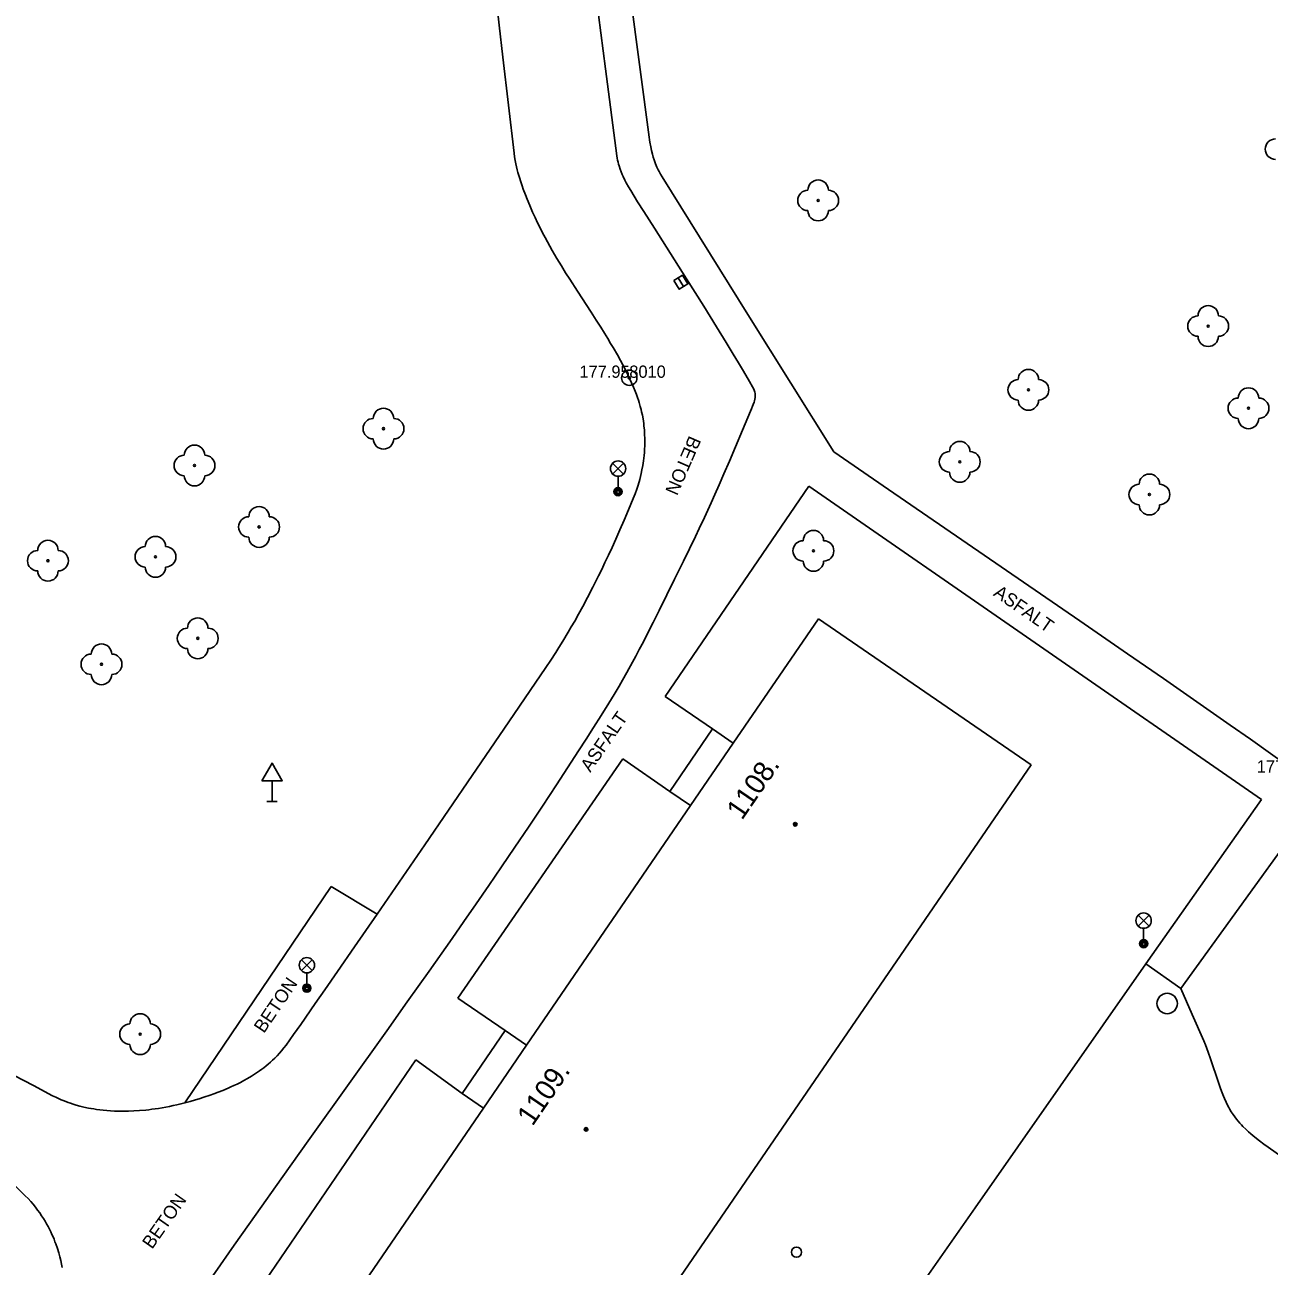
# Model space of a CAD drawing. Extents: x -539515 to -538098, y -1182060 to -1180157.
# Drawn here: x -538886.7 to -538825.8, y -1181224.5 to -1181163.7 of the extents above; entities that cross this region are included whole.
import ezdxf

# ---------------------------------------------------------------- set-up
doc = ezdxf.new("R2010")
doc.units = 0
for name, color, linetype in [('Vrstva 1', 7, 'Continuous'), ('Vrstva 13', 7, 'Continuous'), ('Vrstva 21', 7, 'Continuous'), ('Vrstva 22', 7, 'Continuous'), ('Vrstva 23', 7, 'Continuous'), ('Vrstva 27', 7, 'Continuous'), ('Vrstva 31', 7, 'Continuous'), ('Vrstva 33', 7, 'Continuous'), ('Vrstva 34', 7, 'Continuous'), ('Vrstva 39', 7, 'Continuous'), ('Vrstva 40', 7, 'Continuous'), ('Vrstva 47', 7, 'Continuous'), ('Vrstva 88', 7, 'Continuous')]:
    doc.layers.add(name, color=color, linetype=linetype)

msp = doc.modelspace()

# ---------------------------------------------------------------- linework, layer by layer
at = {"layer": 'Vrstva 1'}
for p, q in [((-538847.83, -1181192.78), (-538837.41, -1181199.92)), ((-538853.007, -1181198.163), (-538855.1, -1181201.22)), ((-538851.991, -1181198.859), (-538853.007, -1181198.163)), ((-538837.41, -1181199.92), (-538868.14, -1181244.73)), ((-538854.083, -1181201.916), (-538855.1, -1181201.22)), ((-538863.155, -1181212.925), (-538865.26, -1181216)), ((-538862.109, -1181213.641), (-538863.155, -1181212.925)), ((-538864.214, -1181216.716), (-538865.26, -1181216))]:
    msp.add_line(p, q, dxfattribs=at)
for points in [[(-538851.991, -1181198.859), (-538847.83, -1181192.78)], [(-538854.083, -1181201.916), (-538851.991, -1181198.859)], [(-538862.109, -1181213.641), (-538854.083, -1181201.916)], [(-538864.214, -1181216.716), (-538862.109, -1181213.641)], [(-538872.38, -1181228.646), (-538864.214, -1181216.716)]]:
    msp.add_lwpolyline(points, dxfattribs=at)
at = {"layer": 'Vrstva 13'}
for p, q in [((-538857.05, -1181162.12), (-538856.11, -1181169.2)), ((-538855.48, -1181171.15), (-538851.275, -1181177.875)), ((-538851.275, -1181177.875), (-538847.07, -1181184.6)), ((-538847.07, -1181184.6), (-538844.398, -1181186.442)), ((-538855.32, -1181196.58), (-538848.29, -1181186.29)), ((-538848.29, -1181186.29), (-538826.14, -1181201.62)), ((-538844.398, -1181186.442), (-538835.034, -1181192.872)), ((-538853.007, -1181198.163), (-538855.32, -1181196.58)), ((-538865.47, -1181211.34), (-538857.4, -1181199.63)), ((-538857.4, -1181199.63), (-538855.1, -1181201.22)), ((-538826.14, -1181201.62), (-538831.8, -1181209.66)), ((-538830.09, -1181210.86), (-538824.35, -1181202.91)), ((-538871.67, -1181205.87), (-538878.83, -1181216.46)), ((-538869.42, -1181207.22), (-538871.67, -1181205.87)), ((-538831.8, -1181209.66), (-538830.09, -1181210.86)), ((-538863.155, -1181212.925), (-538865.47, -1181211.34)), ((-538875.72, -1181226.36), (-538867.52, -1181214.36)), ((-538867.52, -1181214.36), (-538865.26, -1181216))]:
    msp.add_line(p, q, dxfattribs=at)
for points in [[(-538856.11, -1181169.2), (-538856.092, -1181169.327), (-538856.073, -1181169.446), (-538856.032, -1181169.67), (-538855.99, -1181169.865), (-538855.948, -1181170.035), (-538855.906, -1181170.182), (-538855.866, -1181170.309), (-538855.828, -1181170.419), (-538855.793, -1181170.515), (-538855.726, -1181170.679), (-538855.671, -1181170.801), (-538855.627, -1181170.89), (-538855.556, -1181171.022), (-538855.48, -1181171.15)], [(-538835.034, -1181192.872), (-538832.696, -1181194.485), (-538830.945, -1181195.697), (-538829.634, -1181196.609), (-538827.67, -1181197.981)], [(-538827.67, -1181197.981), (-538826.689, -1181198.67), (-538825.71, -1181199.36), (-538825.087, -1181199.804), (-538824.158, -1181200.476), (-538824.08, -1181200.48), (-538823.23, -1181201.15)]]:
    msp.add_lwpolyline(points, dxfattribs=at)
at = {"layer": 'Vrstva 21'}
for radius in [0.375, 0.05]:
    msp.add_circle((-538857.08, -1181180.98), radius, dxfattribs=at)
at = {"layer": 'Vrstva 22'}
for centre in [(-538847.84, -1181172.3), (-538828.75, -1181178.45), (-538837.55, -1181181.57), (-538826.78, -1181182.47), (-538869.11, -1181183.47), (-538878.36, -1181185.27), (-538840.91, -1181185.09), (-538831.63, -1181186.69), (-538875.2, -1181188.28), (-538880.27, -1181189.74), (-538848.07, -1181189.45), (-538885.53, -1181189.93), (-538878.2, -1181193.73), (-538882.91, -1181195), (-538881.02, -1181213.1)]:
    msp.add_circle(centre, 0.05, dxfattribs=at)
for centre, start, end in [((-538825.46, -1181169.79), 90, 270), ((-538847.84, -1181171.8), 0, 180), ((-538848.34, -1181172.3), 90, 270), ((-538847.34, -1181172.3), 270, 90), ((-538847.84, -1181172.8), 180, 0), ((-538828.75, -1181177.95), 0, 180), ((-538829.25, -1181178.45), 90, 270), ((-538828.25, -1181178.45), 270, 90), ((-538828.75, -1181178.95), 180, 0), ((-538837.55, -1181181.07), 0, 180), ((-538838.05, -1181181.57), 90, 270), ((-538837.05, -1181181.57), 270, 90), ((-538826.78, -1181181.97), 0, 180), ((-538837.55, -1181182.07), 180, 0), ((-538827.28, -1181182.47), 90, 270), ((-538826.28, -1181182.47), 270, 90), ((-538869.61, -1181183.47), 90, 270), ((-538869.11, -1181182.97), 0, 180), ((-538868.61, -1181183.47), 270, 90), ((-538826.78, -1181182.97), 180, 0), ((-538878.36, -1181184.77), 0, 180), ((-538869.11, -1181183.97), 180, 0), ((-538840.91, -1181184.59), 0, 180), ((-538878.86, -1181185.27), 90, 270), ((-538877.86, -1181185.27), 270, 90), ((-538841.41, -1181185.09), 90, 270), ((-538840.41, -1181185.09), 270, 90), ((-538878.36, -1181185.77), 180, 0), ((-538840.91, -1181185.59), 180, 0), ((-538831.63, -1181186.19), 0, 180), ((-538832.13, -1181186.69), 90, 270), ((-538831.13, -1181186.69), 270, 90), ((-538875.2, -1181187.78), 0, 180), ((-538831.63, -1181187.19), 180, 0), ((-538875.7, -1181188.28), 90, 270), ((-538874.7, -1181188.28), 270, 90), ((-538848.07, -1181188.95), 0, 180), ((-538885.53, -1181189.43), 0, 180), ((-538880.27, -1181189.24), 0, 180), ((-538875.2, -1181188.78), 180, 0), ((-538848.57, -1181189.45), 90, 270), ((-538847.57, -1181189.45), 270, 90), ((-538886.03, -1181189.93), 90, 270), ((-538885.03, -1181189.93), 270, 90), ((-538880.77, -1181189.74), 90, 270), ((-538879.77, -1181189.74), 270, 90), ((-538880.27, -1181190.24), 180, 0), ((-538848.07, -1181189.95), 180, 0), ((-538885.53, -1181190.43), 180, 0), ((-538878.2, -1181193.23), 0, 180), ((-538878.7, -1181193.73), 90, 270), ((-538877.7, -1181193.73), 270, 90), ((-538882.91, -1181194.5), 0, 180), ((-538883.41, -1181195), 90, 270), ((-538882.41, -1181195), 270, 90), ((-538878.2, -1181194.23), 180, 0), ((-538882.91, -1181195.5), 180, 0), ((-538881.02, -1181212.6), 0, 180), ((-538881.52, -1181213.1), 90, 270), ((-538880.52, -1181213.1), 270, 90), ((-538881.02, -1181213.6), 180, 0)]:
    msp.add_arc(centre, 0.5, start, end, dxfattribs=at)
at = {"layer": 'Vrstva 27'}
msp.add_line((-538854.69, -1181176.092), (-538854.424, -1181176.516), dxfattribs=at)
msp.add_lwpolyline([(-538854.902, -1181176.225), (-538854.636, -1181176.649), (-538854.212, -1181176.383), (-538854.478, -1181175.959)], close=True, dxfattribs=at)
msp.add_circle((-538830.76, -1181211.6), 0.5, dxfattribs=at)
at = {"layer": 'Vrstva 31'}
msp.add_circle((-538848.9, -1181223.77), 0.25, dxfattribs=at)
at = {"layer": 'Vrstva 33'}
for p, q in [((-538857.895, -1181185.69), (-538857.365, -1181185.16)), ((-538857.895, -1181185.16), (-538857.365, -1181185.69)), ((-538857.63, -1181185.8), (-538857.63, -1181186.55)), ((-538832.175, -1181207.81), (-538831.645, -1181207.28)), ((-538832.175, -1181207.28), (-538831.645, -1181207.81)), ((-538831.91, -1181207.92), (-538831.91, -1181208.67)), ((-538873.125, -1181209.99), (-538872.595, -1181209.46)), ((-538873.125, -1181209.46), (-538872.595, -1181209.99)), ((-538872.86, -1181210.1), (-538872.86, -1181210.85))]:
    msp.add_line(p, q, dxfattribs=at)
for centre, radius in [((-538857.63, -1181185.425), 0.375), ((-538857.63, -1181186.55), 0.2), ((-538857.63, -1181186.55), 0.145), ((-538857.63, -1181186.55), 0.0876), ((-538831.91, -1181207.545), 0.375), ((-538831.91, -1181208.67), 0.2), ((-538831.91, -1181208.67), 0.145), ((-538831.91, -1181208.67), 0.0876), ((-538872.86, -1181209.725), 0.375), ((-538872.86, -1181210.85), 0.2), ((-538872.86, -1181210.85), 0.145), ((-538872.86, -1181210.85), 0.0876)]:
    msp.add_circle(centre, radius, dxfattribs=at)
at = {"layer": 'Vrstva 34'}
for p, q in [((-538874.564, -1181200.697), (-538874.564, -1181201.715)), ((-538874.814, -1181201.715), (-538874.314, -1181201.715))]:
    msp.add_line(p, q, dxfattribs=at)
msp.add_lwpolyline([(-538875.064, -1181200.697), (-538874.064, -1181200.697), (-538874.564, -1181199.831)], close=True, dxfattribs=at)
at = {"layer": 'Vrstva 39'}
for centre, radius in [((-538848.962, -1181202.831), 0.09), ((-538848.962, -1181202.831), 0.0398), ((-538859.192, -1181217.758), 0.09), ((-538859.192, -1181217.758), 0.0398)]:
    msp.add_circle(centre, radius, dxfattribs=at)
at = {"layer": 'Vrstva 88'}
for p, q in [((-538858.795, -1181161.59), (-538858.242, -1181165.855)), ((-538859.124, -1181191.735), (-538859.358, -1181192.173)), ((-538831.8, -1181209.66), (-538840.16, -1181221.6)), ((-538868.946, -1181212.929), (-538872.711, -1181218.197)), ((-538840.16, -1181221.6), (-538848.52, -1181233.54))]:
    msp.add_line(p, q, dxfattribs=at)
for points in [[(-538863.682, -1181161.642), (-538863.451, -1181163.727), (-538863.273, -1181165.29), (-538863, -1181167.635), (-538862.72, -1181169.98), (-538862.694, -1181170.168), (-538862.665, -1181170.342), (-538862.633, -1181170.505), (-538862.6, -1181170.657), (-538862.565, -1181170.799), (-538862.53, -1181170.932), (-538862.459, -1181171.179), (-538862.391, -1181171.394)], [(-538858.242, -1181165.855), (-538857.69, -1181170.12), (-538857.673, -1181170.233), (-538857.653, -1181170.338), (-538857.631, -1181170.436), (-538857.607, -1181170.528), (-538857.582, -1181170.613), (-538857.53, -1181170.771), (-538857.479, -1181170.908), (-538857.43, -1181171.026), (-538857.384, -1181171.129), (-538857.299, -1181171.307), (-538857.231, -1181171.438), (-538857.123, -1181171.631), (-538857.01, -1181171.82), (-538856.673, -1181172.365), (-538856.376, -1181172.839), (-538855.852, -1181173.665), (-538855.064, -1181174.9)], [(-538862.391, -1181171.394), (-538862.328, -1181171.581), (-538862.269, -1181171.744), (-538862.162, -1181172.028), (-538862.077, -1181172.24), (-538861.946, -1181172.556), (-538861.81, -1181172.87), (-538861.689, -1181173.14), (-538861.568, -1181173.398)], [(-538861.568, -1181173.398), (-538861.447, -1181173.646), (-538861.326, -1181173.883), (-538861.206, -1181174.112), (-538861.087, -1181174.331), (-538860.97, -1181174.542), (-538860.854, -1181174.746), (-538860.625, -1181175.136), (-538860.405, -1181175.499), (-538860.196, -1181175.837), (-538859.996, -1181176.152), (-538859.617, -1181176.74), (-538858.948, -1181177.768), (-538858.699, -1181178.155), (-538858.482, -1181178.496), (-538858.295, -1181178.797), (-538858.133, -1181179.062), (-538857.993, -1181179.295), (-538857.873, -1181179.5), (-538857.665, -1181179.862), (-538857.513, -1181180.137), (-538857.402, -1181180.345), (-538857.238, -1181180.661), (-538857.08, -1181180.98), (-538856.966, -1181181.224), (-538856.872, -1181181.439), (-538856.795, -1181181.628), (-538856.731, -1181181.795), (-538856.679, -1181181.942), (-538856.636, -1181182.07)], [(-538855.064, -1181174.9), (-538854.671, -1181175.519), (-538854.28, -1181176.14), (-538853.438, -1181177.481), (-538852.808, -1181178.488)], [(-538852.808, -1181178.488), (-538852.341, -1181179.246), (-538851.995, -1181179.816), (-538851.738, -1181180.245), (-538851.548, -1181180.568), (-538851.267, -1181181.053), (-538850.99, -1181181.54), (-538850.95, -1181181.63), (-538850.934, -1181181.687), (-538850.925, -1181181.743), (-538850.92, -1181181.796), (-538850.92, -1181181.847), (-538850.922, -1181181.895), (-538850.927, -1181181.941), (-538850.941, -1181182.027), (-538850.958, -1181182.104), (-538850.977, -1181182.17), (-538851.016, -1181182.287), (-538851.048, -1181182.373)], [(-538856.6, -1181182.183), (-538856.543, -1181182.381), (-538856.504, -1181182.53), (-538856.477, -1181182.642), (-538856.441, -1181182.811), (-538856.41, -1181182.98), (-538856.391, -1181183.1), (-538856.375, -1181183.216), (-538856.362, -1181183.329), (-538856.341, -1181183.55), (-538856.329, -1181183.759), (-538856.323, -1181183.955), (-538856.322, -1181184.14), (-538856.326, -1181184.314), (-538856.334, -1181184.478), (-538856.345, -1181184.631), (-538856.358, -1181184.775), (-538856.372, -1181184.91), (-538856.389, -1181185.036), (-538856.425, -1181185.273), (-538856.463, -1181185.479), (-538856.501, -1181185.659), (-538856.538, -1181185.816), (-538856.573, -1181185.953), (-538856.605, -1181186.072), (-538856.668, -1181186.28), (-538856.718, -1181186.434), (-538856.8, -1181186.663), (-538856.844, -1181186.777), (-538856.89, -1181186.89), (-538857.12, -1181187.44), (-538857.338, -1181187.951), (-538857.544, -1181188.426), (-538857.741, -1181188.869), (-538857.927, -1181189.281), (-538858.104, -1181189.666), (-538858.272, -1181190.024), (-538858.431, -1181190.357), (-538858.583, -1181190.669), (-538858.727, -1181190.959), (-538858.864, -1181191.23)], [(-538856.636, -1181182.07), (-538856.6, -1181182.183)], [(-538851.048, -1181182.373), (-538851.099, -1181182.499), (-538851.15, -1181182.62), (-538851.54, -1181183.548), (-538851.882, -1181184.357), (-538852.184, -1181185.064), (-538852.451, -1181185.68), (-538852.687, -1181186.219), (-538852.895, -1181186.689), (-538853.079, -1181187.099), (-538853.406, -1181187.816), (-538853.655, -1181188.351), (-538853.845, -1181188.752), (-538854.134, -1181189.352), (-538854.43, -1181189.95), (-538854.867, -1181190.832)], [(-538854.867, -1181190.832), (-538855.627, -1181192.375), (-538855.913, -1181192.951), (-538856.167, -1181193.454), (-538856.391, -1181193.893), (-538856.59, -1181194.275), (-538856.766, -1181194.609), (-538856.922, -1181194.899), (-538857.2, -1181195.405), (-538857.413, -1181195.783), (-538857.576, -1181196.064), (-538857.825, -1181196.484), (-538858.08, -1181196.9), (-538858.456, -1181197.5), (-538858.829, -1181198.09), (-538859.197, -1181198.669), (-538859.562, -1181199.237)], [(-538858.864, -1181191.23), (-538859.124, -1181191.735)], [(-538859.358, -1181192.173), (-538859.567, -1181192.554), (-538859.753, -1181192.885), (-538859.918, -1181193.173), (-538860.066, -1181193.424), (-538860.328, -1181193.861), (-538860.53, -1181194.186), (-538860.684, -1181194.429), (-538860.919, -1181194.791), (-538861.16, -1181195.15), (-538863.22, -1181198.173), (-538864.767, -1181200.437)], [(-538859.562, -1181199.237), (-538859.923, -1181199.796), (-538860.637, -1181200.892)], [(-538864.767, -1181200.437), (-538867.092, -1181203.829), (-538869.42, -1181207.22)], [(-538860.637, -1181200.892), (-538861.336, -1181201.949), (-538862.017, -1181202.97), (-538862.682, -1181203.956), (-538863.329, -1181204.909), (-538863.96, -1181205.829), (-538864.574, -1181206.719), (-538865.171, -1181207.579), (-538865.751, -1181208.411)], [(-538869.42, -1181207.22), (-538870.525, -1181208.827), (-538871.355, -1181210.031), (-538871.979, -1181210.932), (-538872.45, -1181211.607)], [(-538865.751, -1181208.411), (-538866.881, -1181210.018)], [(-538866.881, -1181210.018), (-538867.945, -1181211.522), (-538868.946, -1181212.929)], [(-538830.09, -1181210.86), (-538829.53, -1181212.145), (-538828.97, -1181213.43), (-538828.888, -1181213.625), (-538828.816, -1181213.809), (-538828.751, -1181213.982), (-538828.635, -1181214.31), (-538828.252, -1181215.465), (-538828.15, -1181215.753), (-538828.068, -1181215.967), (-538828.004, -1181216.127), (-538827.954, -1181216.246), (-538827.874, -1181216.424), (-538827.79, -1181216.6), (-538827.749, -1181216.68), (-538827.708, -1181216.756), (-538827.622, -1181216.9), (-538827.536, -1181217.03), (-538827.451, -1181217.15), (-538827.367, -1181217.259), (-538827.285, -1181217.359), (-538827.206, -1181217.45), (-538827.129, -1181217.534), (-538827.056, -1181217.611), (-538826.914, -1181217.753), (-538826.785, -1181217.873), (-538826.67, -1181217.975), (-538826.567, -1181218.062), (-538826.385, -1181218.211), (-538826.245, -1181218.319), (-538826.033, -1181218.477), (-538825.82, -1181218.63)], [(-538872.45, -1181211.607), (-538873.162, -1181212.619), (-538873.52, -1181213.124), (-538873.88, -1181213.63), (-538873.987, -1181213.774), (-538874.095, -1181213.908), (-538874.204, -1181214.035), (-538874.314, -1181214.155), (-538874.424, -1181214.267), (-538874.534, -1181214.373), (-538874.643, -1181214.472), (-538874.751, -1181214.566), (-538874.859, -1181214.655), (-538874.965, -1181214.739), (-538875.069, -1181214.818), (-538875.173, -1181214.893), (-538875.274, -1181214.964), (-538875.374, -1181215.03), (-538875.571, -1181215.156), (-538875.759, -1181215.268), (-538875.939, -1181215.369), (-538876.111, -1181215.46), (-538876.274, -1181215.542), (-538876.428, -1181215.616), (-538876.574, -1181215.684), (-538876.712, -1181215.745), (-538876.973, -1181215.854), (-538877.203, -1181215.945), (-538877.406, -1181216.02), (-538877.584, -1181216.084), (-538877.897, -1181216.188), (-538878.131, -1181216.262), (-538878.307, -1181216.314), (-538878.569, -1181216.389), (-538878.83, -1181216.46), (-538879.026, -1181216.51), (-538879.218, -1181216.556), (-538879.406, -1181216.598), (-538879.589, -1181216.636), (-538879.768, -1181216.671), (-538879.943, -1181216.702), (-538880.113, -1181216.73), (-538880.278, -1181216.755), (-538880.439, -1181216.777)], [(-538881.582, -1181216.868), (-538881.827, -1181216.871), (-538882.056, -1181216.87), (-538882.27, -1181216.863), (-538882.47, -1181216.852), (-538882.657, -1181216.839), (-538882.832, -1181216.822), (-538882.995, -1181216.803), (-538883.147, -1181216.783), (-538883.289, -1181216.761), (-538883.422, -1181216.739), (-538883.545, -1181216.715), (-538883.775, -1181216.666), (-538883.974, -1181216.617), (-538884.147, -1181216.57), (-538884.296, -1181216.525), (-538884.426, -1181216.483), (-538884.539, -1181216.444), (-538884.734, -1181216.37), (-538884.878, -1181216.311), (-538884.985, -1181216.264), (-538885.144, -1181216.189), (-538885.3, -1181216.11), (-538886.24, -1181215.615), (-538887.18, -1181215.12)], [(-538880.439, -1181216.777), (-538880.596, -1181216.796), (-538880.748, -1181216.813), (-538881.044, -1181216.839), (-538881.322, -1181216.857), (-538881.582, -1181216.868)], [(-538872.711, -1181218.197), (-538874.12, -1181220.173), (-538875.348, -1181221.906), (-538876.418, -1181223.425), (-538877.349, -1181224.758), (-538878.159, -1181225.927)], [(-538825.82, -1181218.63), (-538824.08, -1181219.857), (-538822.34, -1181221.083), (-538821.47, -1181221.697), (-538820.6, -1181222.31), (-538820.508, -1181222.371), (-538820.419, -1181222.424), (-538820.334, -1181222.47), (-538820.251, -1181222.51), (-538820.173, -1181222.545), (-538820.097, -1181222.576), (-538820.026, -1181222.602), (-538819.89, -1181222.646), (-538819.769, -1181222.679), (-538819.661, -1181222.704), (-538819.567, -1181222.722), (-538819.484, -1181222.735), (-538819.338, -1181222.753), (-538819.228, -1181222.762), (-538819.146, -1181222.766), (-538819.024, -1181222.769), (-538818.902, -1181222.766), (-538818.586, -1181222.753), (-538818.27, -1181222.74)], [(-538887.97, -1181219.725), (-538886.64, -1181221.01), (-538886.503, -1181221.147), (-538886.375, -1181221.286), (-538886.254, -1181221.426), (-538886.14, -1181221.566), (-538886.034, -1181221.705), (-538885.934, -1181221.845), (-538885.84, -1181221.983), (-538885.752, -1181222.12), (-538885.67, -1181222.255), (-538885.594, -1181222.388), (-538885.523, -1181222.519), (-538885.456, -1181222.648), (-538885.394, -1181222.774), (-538885.336, -1181222.898), (-538885.283, -1181223.019), (-538885.233, -1181223.138), (-538885.187, -1181223.254), (-538885.144, -1181223.367), (-538885.067, -1181223.588), (-538885.002, -1181223.797), (-538884.947, -1181223.995), (-538884.901, -1181224.182), (-538884.863, -1181224.357), (-538884.832, -1181224.522)]]:
    msp.add_lwpolyline(points, dxfattribs=at)

# ---------------------------------------------------------------- texts
at = {"layer": 'Vrstva 22'}
for s, p in [('177.95 ', (-538859.519, -1181180.98)), ('177.78 ', (-538826.374, -1181200.3))]:
    msp.add_text(s, height=0.6, dxfattribs=at).set_placement(p)
at = {"layer": 'Vrstva 23'}
msp.add_text('8010', height=0.6, dxfattribs=at).set_placement((-538857.08, -1181180.98))
at = {"layer": 'Vrstva 40'}
for s, rotation, p in [('BETON', 246.50502, (-538854.144, -1181183.774)), ('ASFALT', 325.31292, (-538839.307, -1181191.614)), ('ASFALT', 55.42715, (-538858.99, -1181200.319)), ('BETON', 55.937, (-538874.961, -1181213.091)), ('BETON', 55.04738, (-538880.434, -1181223.655))]:
    msp.add_text(s, height=0.65, rotation=rotation, dxfattribs=at).set_placement(p)
at = {"layer": 'Vrstva 47'}
for s, p in [('1108.', (-538851.566, -1181202.665)), ('1109.', (-538861.817, -1181217.64))]:
    msp.add_text(s, height=1, rotation=55.60821, dxfattribs=at).set_placement(p)

doc.saveas('drawing.dxf')
